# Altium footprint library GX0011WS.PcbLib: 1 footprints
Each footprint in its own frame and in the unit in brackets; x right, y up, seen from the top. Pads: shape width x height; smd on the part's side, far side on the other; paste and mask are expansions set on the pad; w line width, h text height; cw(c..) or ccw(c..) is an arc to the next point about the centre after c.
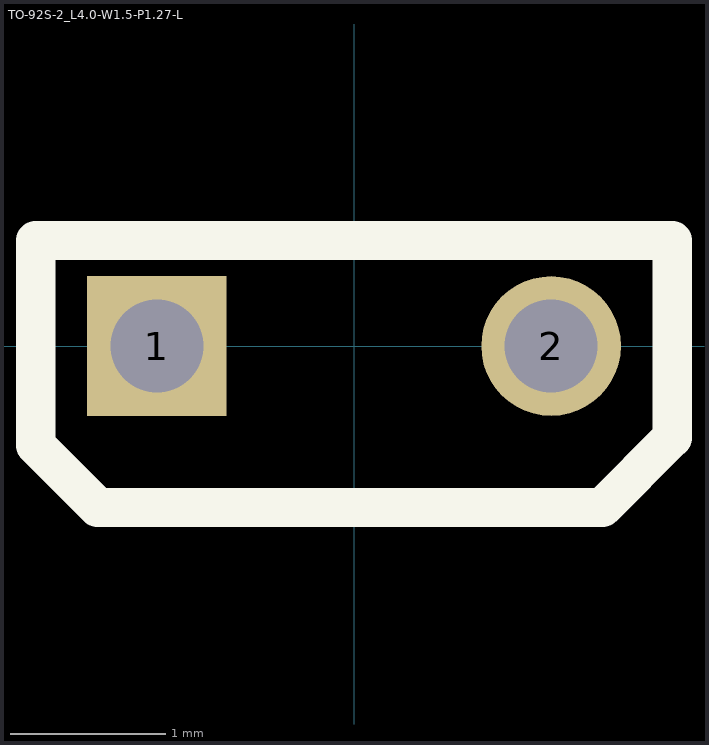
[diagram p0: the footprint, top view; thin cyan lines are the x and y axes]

## TO-92S-2_L4.0-W1.5-P1.27-L [mm]
pads (2):
  rect 0.9x0.9 hole 0.6: 1(-1.27,0)
  round 0.9 hole 0.6: 2(1.27,0)
Top Overlay:
  lines w0.254: 1.6,-1.04 -1.6,-1.04 -1.65,-1.04 -2.05,-0.64 -2.05,0.68 2.05,0.68 2.05,-0.59 ; 1.6,-1.039 2.05,-0.59
3D body "TO-92S-2.STEP": height 5.48, standoff -5, extent -2.05,-0.991 2.05,0.59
